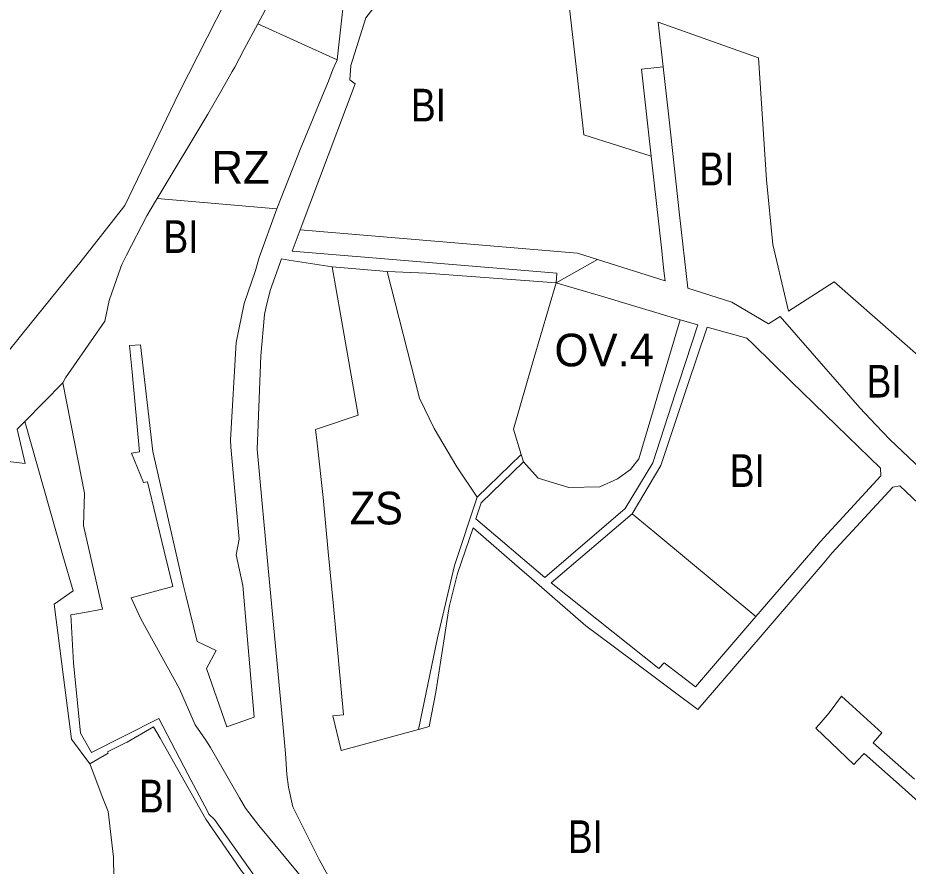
# Model space of a CAD drawing. Extents: x -650451 to -642268, y -1075216 to -1066610.
# Drawn here: x -650200.3 to -649873.5, y -1069851.3 to -1069539.9 of the extents above; entities that cross this region are included whole.
import ezdxf

# ---------------------------------------------------------------- set-up
doc = ezdxf.new("R2010")
doc.units = 0
doc.header["$LTSCALE"] = 4.8
for name, color, linetype, lineweight in [('11', 7, 'Continuous', 13), ('15', 7, 'Continuous', 13), ('2', 7, 'Continuous', 13), ('25', 7, 'Continuous', 13), ('41', 7, 'Continuous', 13), ('46', 7, 'Continuous', 13), ('6', 7, 'Continuous', 13)]:
    doc.layers.add(name, color=color, linetype=linetype, lineweight=lineweight)
doc.layers.add('62', color=7, linetype='Continuous')

msp = doc.modelspace()

# ---------------------------------------------------------------- linework, layer by layer
at = {"layer": '11'}
for points in [[(-650015.53, -1069700.21), (-650018.31, -1069690.89), (-650011.15, -1069665.82), (-650002.65, -1069637.14)], [(-650002.65, -1069637.14), (-649999.03, -1069638.22), (-649987.32, -1069641.73), (-649957.15, -1069650.76)], [(-649957.15, -1069650.76), (-649965.45, -1069678.6), (-649966.59, -1069682.44), (-649972.35, -1069701.78), (-649975.45, -1069705.65), (-649980.22, -1069709.07), (-649986.69, -1069712.03), (-649998, -1069712.26), (-650009.29, -1069708.92), (-650014.74, -1069702.9), (-650015.53, -1069700.21)]]:
    msp.add_lwpolyline(points, dxfattribs=at)
at = {"layer": '15'}
msp.add_line((-650197.7, -1069688.08), (-650183.82, -1069673.87), dxfattribs=at)
for points in [[(-650083.1, -1069555.34), (-650079, -1069518.93), (-650061.51, -1069483.79), (-650045.72, -1069459.1), (-650040.012, -1069461.999)], [(-650040.012, -1069461.999), (-650052.68, -1069478.83), (-650072.18, -1069516.15), (-650072.79, -1069517.3), (-650073.42, -1069526.19), (-650069.92, -1069527.41), (-650064.71, -1069529.78), (-650072.51, -1069539.93), (-650078.05, -1069557.42), (-650078.46, -1069562.62), (-650076.5, -1069564.13), (-650089.55, -1069598.9), (-650096.627, -1069617.746)], [(-650105.19, -1069610.01), (-650096.36, -1069587.63), (-650093, -1069579.43), (-650089.68, -1069571.36), (-650086.32, -1069563.16), (-650084.69, -1069558.83), (-650083.34, -1069555.91), (-650083.1, -1069555.34)], [(-649967.81, -1069590.74), (-649971.38, -1069558.79), (-649963.43, -1069557.91)], [(-649963.43, -1069557.91), (-649961.38, -1069576.24), (-649957.37, -1069612.18), (-649954.38, -1069639.099), (-649938.2, -1069644.23), (-649924.8, -1069652.19), (-649920.45, -1069649.53), (-649896.97, -1069676.43), (-649891.19, -1069683.08), (-649885.41, -1069689.3), (-649880.23, -1069694.74), (-649871.1, -1069703.42), (-649865.16, -1069709.14), (-649855.95, -1069717.81), (-649840.59, -1069702.06), (-649833.941, -1069695.24)], [(-649987.49, -1069628.6), (-649962.71, -1069636.458), (-649963.011, -1069633.76), (-649963.26, -1069631.49), (-649964.066, -1069624.3), (-649967.81, -1069590.74)], [(-650090.16, -1069862.54), (-650108.28, -1069840.67), (-650111.83, -1069836.4), (-650116.74, -1069830.03), (-650118.92, -1069826.21), (-650129.55, -1069807.68), (-650131.27, -1069805.04), (-650135.25, -1069799.36), (-650140.99, -1069786.24), (-650155.1, -1069760.48), (-650158.74, -1069752.8), (-650153.86, -1069751.49), (-650143.37, -1069748.68), (-650146.53, -1069735.65), (-650152.7, -1069710.16), (-650154.18, -1069710.42), (-650158.59, -1069699.65), (-650155.62, -1069699.22), (-650158.38, -1069669.92), (-650159.3, -1069660.17), (-650155.3, -1069659.94), (-650150.72, -1069699.05), (-650139.6, -1069747.91), (-650138.51, -1069752.27), (-650134.41, -1069768.77), (-650127.52, -1069772.07), (-650131.1, -1069778.76), (-650123.63, -1069800.11), (-650113.5, -1069796.6), (-650117.65, -1069748.28), (-650120.13, -1069737), (-650119.1, -1069731.21), (-650122.13, -1069697.33), (-650122.26, -1069694.82), (-650120.2, -1069659.04), (-650117.18, -1069644.8), (-650113.01, -1069632.68), (-650111.69, -1069627.86), (-650105.19, -1069610.01)], [(-650096.627, -1069617.746), (-650099.55, -1069625.53), (-650002.39, -1069633.65), (-650002.65, -1069637.14)], [(-650084.9, -1069631.28), (-650100.78, -1069628.81), (-650103.56, -1069628.38), (-650107.67, -1069639.98), (-650109.21, -1069646.43), (-650109.79, -1069648.83), (-650111.14, -1069664), (-650112.22, -1069692.23), (-650112.45, -1069698.2), (-650110.6, -1069718.12), (-650108.74, -1069738.03), (-650103.19, -1069797.78), (-650102.06, -1069809.88), (-650101.56, -1069817.62), (-650100.93, -1069822.28), (-650099.33, -1069829.47), (-650089.66, -1069848.89), (-650086.22, -1069855.06)], [(-649957.15, -1069650.76), (-649987.32, -1069641.73), (-649999.03, -1069638.22), (-650002.65, -1069637.14), (-649987.49, -1069628.6)], [(-650064.77, -1069633.06), (-650080.52, -1069631.67), (-650084.9, -1069631.28)], [(-650002.65, -1069637.14), (-650050.26, -1069633.65), (-650064.77, -1069633.06)], [(-650014.74, -1069702.9), (-650030.26, -1069717.96), (-650032.13, -1069723.75), (-650006.85, -1069745.3), (-649977.31, -1069720.05), (-649967.27, -1069703.29), (-649958.87, -1069677.59), (-649957.54, -1069673.5), (-649950.69, -1069652.54), (-649957.15, -1069650.76)], [(-649929.38, -1069759.65), (-649909.27, -1069736.29), (-649905.82, -1069732.28), (-649883.49, -1069708.04), (-649883.6, -1069705.18), (-649899.74, -1069689.5), (-649916.38, -1069673.34), (-649930.41, -1069659.71), (-649932.7, -1069657.49), (-649947.32, -1069653.47), (-649954.47, -1069674.82), (-649964.3, -1069704.18), (-649974.86, -1069721.96)], [(-650183.82, -1069673.87), (-650178.16, -1069702.51), (-650175.82, -1069714.32), (-650176.23, -1069726.19), (-650169.26, -1069756.93), (-650177.18, -1069758.38), (-650180.81, -1069759.05), (-650179.85, -1069776.68), (-650177.29, -1069802.53), (-650173.21, -1069809.54), (-650148.59, -1069797.1), (-650137.86, -1069817.54), (-650130.61, -1069831.34), (-650130.15, -1069832.23), (-650128.08, -1069834.19), (-650112.97, -1069855.55)], [(-650173.87, -1069813.75), (-650180.63, -1069804.63), (-650183.51, -1069781.92), (-650186.91, -1069755.15), (-650180.04, -1069750.27), (-650183.73, -1069737.28), (-650197.7, -1069688.08)], [(-650053.2, -1069801.11), (-650046.28, -1069767.47), (-650040.01, -1069740.9), (-650031.64, -1069715.9), (-650015.53, -1069700.21), (-650014.74, -1069702.9)], [(-649865.19, -1069722.43), (-649876.61, -1069711.74), (-649879.07, -1069712.16), (-649901.42, -1069736.29), (-649903.24, -1069738.49), (-649905.05, -1069740.69), (-649927.86, -1069767.23), (-649950.7, -1069793.76), (-649959.43, -1069787.24), (-649971.65, -1069778.08), (-649982.24, -1069770.15), (-649991.78, -1069763.02), (-650012.77, -1069744.8), (-650015.15, -1069742.74), (-650033.2, -1069727.08), (-650038.92, -1069743.89), (-650041.79, -1069755.67), (-650042.24, -1069757.54), (-650043.81, -1069767.85), (-650046.82, -1069787.47), (-650049.34, -1069800.06), (-650053.2, -1069801.11)], [(-649974.86, -1069721.96), (-650004.59, -1069747.27), (-649965, -1069778.7), (-649963, -1069776.7), (-649951.56, -1069785.42), (-649929.38, -1069759.65)], [(-649858.72, -1069837.54), (-649874.62, -1069823.28), (-649889.7, -1069809.88), (-649892.16, -1069812.65), (-649893.39, -1069814.03), (-649907.42, -1069800.68), (-649906.21, -1069799.28), (-649902.52, -1069795), (-649897.98, -1069788.95), (-649883.11, -1069802.36), (-649886.3, -1069805.96), (-649871.2, -1069819.33)], [(-650110.99, -1069894.94), (-650109.09, -1069872.83), (-650110.01, -1069867.87), (-650111.13, -1069861.88), (-650118.34, -1069852.9), (-650121.5, -1069848.27), (-650131.29, -1069833.99), (-650148.09, -1069804.36), (-650150.51, -1069800.1), (-650160.21, -1069805.77), (-650160.23, -1069805.73), (-650167.33, -1069809.33), (-650167.1, -1069809.79), (-650173.87, -1069813.75)]]:
    msp.add_lwpolyline(points, dxfattribs=at)
at = {"layer": '2'}
for points in [[(-650096.627, -1069617.746), (-650089.55, -1069598.9), (-650076.5, -1069564.13), (-650078.46, -1069562.62), (-650078.05, -1069557.42), (-650072.51, -1069539.93), (-650064.71, -1069529.78), (-650069.92, -1069527.41), (-650073.42, -1069526.19), (-650072.79, -1069517.3), (-650072.18, -1069516.15), (-650052.68, -1069478.83), (-650040.012, -1069461.999)], [(-650000.59, -1069511.15), (-649998.81, -1069527.07), (-649998.5, -1069529.88), (-649994.794, -1069563.119), (-649992.589, -1069582.88), (-649967.81, -1069590.74)], [(-649963.43, -1069557.91), (-649965.26, -1069541.51), (-649928.48, -1069554.57), (-649925.53, -1069599.38), (-649923.17, -1069623.14), (-649918.35, -1069643.45), (-649917.38, -1069647.56), (-649900.64, -1069636.78), (-649877.82, -1069656.83), (-649859.96, -1069672.53), (-649859.17, -1069673.22), (-649857.49, -1069671.46), (-649833.941, -1069695.24)], [(-649833.941, -1069695.24), (-649840.59, -1069702.06), (-649855.95, -1069717.81), (-649865.16, -1069709.14), (-649871.1, -1069703.42), (-649880.23, -1069694.74), (-649885.41, -1069689.3), (-649891.19, -1069683.08), (-649896.97, -1069676.43), (-649920.45, -1069649.53), (-649924.8, -1069652.19), (-649938.2, -1069644.23), (-649954.38, -1069639.099), (-649957.37, -1069612.18), (-649961.38, -1069576.24), (-649963.43, -1069557.91)], [(-649967.81, -1069590.74), (-649964.066, -1069624.3), (-649963.26, -1069631.49), (-649963.011, -1069633.76), (-649962.71, -1069636.458), (-649987.49, -1069628.6)], [(-650183.82, -1069673.87), (-650182.78, -1069672.09), (-650168.4, -1069651.27), (-650166.82, -1069643.66), (-650163.17, -1069633.49), (-650162.1, -1069630.49), (-650160.4, -1069626.97), (-650152.96, -1069612.53), (-650149.77, -1069607.22), (-650149.19, -1069606.26), (-650105.19, -1069610.01)], [(-650105.19, -1069610.01), (-650111.69, -1069627.86), (-650113.01, -1069632.68), (-650117.18, -1069644.8), (-650120.2, -1069659.04), (-650122.26, -1069694.82), (-650122.13, -1069697.33), (-650119.1, -1069731.21), (-650120.13, -1069737), (-650117.65, -1069748.28), (-650113.5, -1069796.6), (-650123.63, -1069800.11), (-650131.1, -1069778.76), (-650127.52, -1069772.07), (-650134.41, -1069768.77), (-650138.51, -1069752.27), (-650139.6, -1069747.91), (-650150.72, -1069699.05), (-650155.3, -1069659.94), (-650159.3, -1069660.17), (-650158.38, -1069669.92), (-650155.62, -1069699.22), (-650158.59, -1069699.65), (-650154.18, -1069710.42), (-650152.7, -1069710.16), (-650146.53, -1069735.65), (-650143.37, -1069748.68), (-650153.86, -1069751.49), (-650158.74, -1069752.8), (-650155.1, -1069760.48), (-650140.99, -1069786.24), (-650135.25, -1069799.36), (-650131.27, -1069805.04), (-650129.55, -1069807.68), (-650118.92, -1069826.21), (-650116.74, -1069830.03), (-650111.83, -1069836.4), (-650108.28, -1069840.67), (-650090.16, -1069862.54)], [(-649987.49, -1069628.6), (-649994.913, -1069626.246), (-650096.627, -1069617.746)], [(-650086.22, -1069855.06), (-650089.66, -1069848.89), (-650099.33, -1069829.47), (-650100.93, -1069822.28), (-650101.56, -1069817.62), (-650102.06, -1069809.88), (-650103.19, -1069797.78), (-650108.74, -1069738.03), (-650110.6, -1069718.12), (-650112.45, -1069698.2), (-650112.22, -1069692.23), (-650111.14, -1069664), (-650109.79, -1069648.83), (-650109.21, -1069646.43), (-650107.67, -1069639.98), (-650103.56, -1069628.38), (-650100.78, -1069628.81), (-650084.9, -1069631.28)], [(-650084.9, -1069631.28), (-650081.73, -1069649.38), (-650075.35, -1069685.77), (-650089.57, -1069690.53), (-650090.98, -1069691), (-650090.41, -1069696.07), (-650088.19, -1069716.03), (-650086.34, -1069735.95), (-650084.48, -1069755.86), (-650080.78, -1069795.7), (-650084.63, -1069796.06), (-650081.66, -1069808.87), (-650053.2, -1069801.11)], [(-649974.86, -1069721.96), (-649964.3, -1069704.18), (-649954.47, -1069674.82), (-649947.32, -1069653.47), (-649932.7, -1069657.49), (-649930.41, -1069659.71), (-649916.38, -1069673.34), (-649899.74, -1069689.5), (-649883.6, -1069705.18), (-649883.49, -1069708.04), (-649905.82, -1069732.28), (-649909.27, -1069736.29), (-649929.38, -1069759.65)], [(-650112.97, -1069855.55), (-650128.08, -1069834.19), (-650130.15, -1069832.23), (-650130.61, -1069831.34), (-650137.86, -1069817.54), (-650148.59, -1069797.1), (-650173.21, -1069809.54), (-650177.29, -1069802.53), (-650179.85, -1069776.68), (-650180.81, -1069759.05), (-650177.18, -1069758.38), (-650169.26, -1069756.93), (-650176.23, -1069726.19), (-650175.82, -1069714.32), (-650178.16, -1069702.51), (-650183.82, -1069673.87)], [(-650053.2, -1069801.11), (-650049.34, -1069800.06), (-650046.82, -1069787.47), (-650043.81, -1069767.85), (-650042.24, -1069757.54), (-650041.79, -1069755.67), (-650038.92, -1069743.89), (-650033.2, -1069727.08), (-650015.15, -1069742.74), (-650012.77, -1069744.8), (-649991.78, -1069763.02), (-649982.24, -1069770.15), (-649971.65, -1069778.08), (-649959.43, -1069787.24), (-649950.7, -1069793.76), (-649927.86, -1069767.23), (-649905.05, -1069740.69), (-649903.24, -1069738.49), (-649901.42, -1069736.29), (-649879.07, -1069712.16), (-649876.61, -1069711.74), (-649865.19, -1069722.43)], [(-649929.38, -1069759.65), (-649966.52, -1069728.87), (-649974.86, -1069721.96)], [(-649871.2, -1069819.33), (-649886.3, -1069805.96), (-649883.11, -1069802.36), (-649897.98, -1069788.95), (-649902.52, -1069795), (-649906.21, -1069799.28), (-649907.42, -1069800.68), (-649893.39, -1069814.03), (-649892.16, -1069812.65), (-649889.7, -1069809.88), (-649874.62, -1069823.28), (-649858.72, -1069837.54)], [(-650173.87, -1069813.75), (-650167.1, -1069809.79), (-650167.33, -1069809.33), (-650160.23, -1069805.73), (-650160.21, -1069805.77), (-650150.51, -1069800.1), (-650148.09, -1069804.36), (-650131.29, -1069833.99), (-650121.5, -1069848.27), (-650118.34, -1069852.9), (-650111.13, -1069861.88), (-650110.01, -1069867.87), (-650109.09, -1069872.83), (-650110.99, -1069894.94)], [(-650164.75, -1069885.61), (-650165.06, -1069855.42), (-650165.14, -1069847.93), (-650167.17, -1069831.25), (-650169.29, -1069825.71), (-650172.79, -1069816.55), (-650173.87, -1069813.75)]]:
    msp.add_lwpolyline(points, dxfattribs=at)
at = {"layer": '25'}
for points in [[(-650002.11, -1069382.8), (-650003.73, -1069384.71), (-650026.33, -1069411.47), (-650057.49, -1069448.18), (-650060.29, -1069451.7), (-650062.17, -1069454.05), (-650063.12, -1069453.54), (-650072.5, -1069466.44), (-650081.29, -1069484.35), (-650112.18, -1069542.11)], [(-650205.82, -1069664.8), (-650198.33, -1069655.56), (-650180.79, -1069633.89), (-650177.51, -1069629.84), (-650160.99, -1069608.81), (-650141.06, -1069567.33), (-650113.74, -1069513.61)], [(-650112.18, -1069542.11), (-650117.19, -1069551.46), (-650120.7, -1069558.03), (-650121.59, -1069559.59), (-650125.94, -1069567.19), (-650130.57, -1069575.27), (-650149.19, -1069606.26)], [(-650149.19, -1069606.26), (-650149.77, -1069607.22), (-650152.96, -1069612.53), (-650160.4, -1069626.97), (-650162.1, -1069630.49), (-650163.17, -1069633.49), (-650166.82, -1069643.66), (-650168.4, -1069651.27), (-650182.78, -1069672.09), (-650183.82, -1069673.87), (-650197.7, -1069688.08)], [(-650197.7, -1069688.08), (-650200.5, -1069690.94), (-650197.58, -1069703.52), (-650211.41, -1069701.88), (-650246.69, -1069728.77), (-650255.716, -1069731.162), (-650259.97, -1069732.29), (-650264.91, -1069735.69), (-650270.059, -1069739.232)]]:
    msp.add_lwpolyline(points, dxfattribs=at)
at = {"layer": '41'}
for points in [[(-650053.2, -1069801.11), (-650081.66, -1069808.87), (-650084.63, -1069796.06), (-650080.78, -1069795.7), (-650084.48, -1069755.86), (-650086.34, -1069735.95), (-650088.19, -1069716.03), (-650090.41, -1069696.07), (-650090.98, -1069691), (-650089.57, -1069690.53), (-650075.35, -1069685.77), (-650081.73, -1069649.38), (-650084.9, -1069631.28)], [(-650084.9, -1069631.28), (-650080.52, -1069631.67), (-650064.77, -1069633.06)], [(-650064.77, -1069633.06), (-650052.88, -1069679.49), (-650047.45, -1069690.69), (-650039.11, -1069704.76), (-650031.64, -1069715.9)], [(-650031.64, -1069715.9), (-650040.01, -1069740.9), (-650046.28, -1069767.47), (-650053.2, -1069801.11)]]:
    msp.add_lwpolyline(points, dxfattribs=at)
at = {"layer": '46'}
for points in [[(-650255.716, -1069731.162), (-650246.69, -1069728.77), (-650211.41, -1069701.88), (-650197.58, -1069703.52), (-650200.5, -1069690.94), (-650197.7, -1069688.08)], [(-650197.7, -1069688.08), (-650183.73, -1069737.28), (-650180.04, -1069750.27), (-650186.91, -1069755.15), (-650183.51, -1069781.92), (-650180.63, -1069804.63), (-650173.87, -1069813.75)], [(-650173.87, -1069813.75), (-650172.79, -1069816.55), (-650169.29, -1069825.71), (-650167.17, -1069831.25), (-650165.14, -1069847.93), (-650165.06, -1069855.42), (-650164.75, -1069885.61), (-650260.645, -1069868.536)]]:
    msp.add_lwpolyline(points, dxfattribs=at)
at = {"layer": '6'}
for points in [[(-650149.19, -1069606.26), (-650130.57, -1069575.27), (-650125.94, -1069567.19), (-650121.59, -1069559.59), (-650120.7, -1069558.03), (-650117.19, -1069551.46), (-650112.18, -1069542.11), (-650083.1, -1069555.34)], [(-650083.1, -1069555.34), (-650083.34, -1069555.91), (-650084.69, -1069558.83), (-650086.32, -1069563.16), (-650089.68, -1069571.36), (-650093, -1069579.43), (-650096.36, -1069587.63), (-650105.19, -1069610.01), (-650149.19, -1069606.26)]]:
    msp.add_lwpolyline(points, dxfattribs=at)

# ---------------------------------------------------------------- texts
at = {"layer": '62'}
for s, width, p in [('BI', 0.85, (-650056.002, -1069577.958)), ('BI', 0.85, (-649950.152, -1069601.384)), ('BI', 0.85, (-650146.852, -1069626.21)), ('BI', 0.85, (-649888.751, -1069679.279)), ('BI', 0.85, (-649938.973, -1069712.103)), ('ZS', 0.95, (-650078.448, -1069725.858)), ('BI', 0.85, (-650155.808, -1069831.572)), ('BI', 0.85, (-649998.42, -1069846.474))]:
    msp.add_text(s, height=12, dxfattribs=dict(at, width=width)).set_placement(p)
for s, p in [('RZ', (-650129.21, -1069600.751)), ('OV.4', (-650003.329, -1069667.835))]:
    msp.add_text(s, height=12, dxfattribs=at).set_placement(p)

doc.saveas('drawing.dxf')
